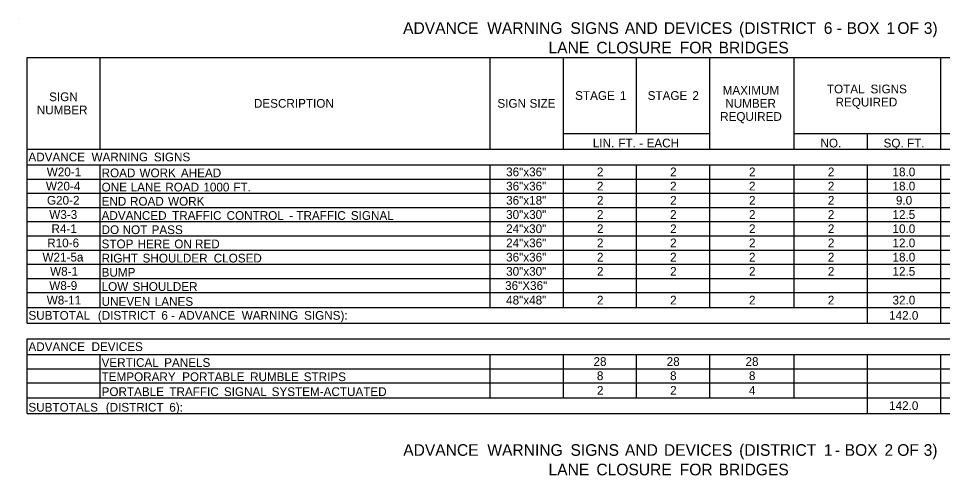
# Model space of a CAD drawing. Extents: x 542596 to 1930787, y -1948294 to 596640.
# Drawn here: x 544431 to 545065, y -1946350 to -1946037 of the extents above; entities that cross this region are included whole.
import ezdxf

# ---------------------------------------------------------------- set-up
doc = ezdxf.new("R2010")
doc.units = 0
doc.layers.add('Default', color=7, linetype='Continuous')

msp = doc.modelspace()

# ---------------------------------------------------------------- linework, layer by layer
at = {"layer": 'Default'}
for p, q in [((544430.58, -1946036.6), (544430.58, -1946036.6)), ((544436.43, -1946063.41), (545325.15, -1946063.41)), ((544436.43, -1946245.74), (544436.43, -1946063.41)), ((544436.43, -1946245.74), (544436.43, -1946063.41)), ((544486.65, -1946126.3), (544486.65, -1946063.41)), ((544754.28, -1946126.3), (544754.28, -1946063.41)), ((544804.5, -1946126.3), (544804.5, -1946063.41)), ((544854.71, -1946115.57), (544854.71, -1946063.41)), ((544904.92, -1946126.3), (544904.92, -1946063.41)), ((544962.93, -1946126.3), (544962.93, -1946063.41)), ((545063.36, -1946126.3), (545063.36, -1946063.41)), ((544804.5, -1946115.57), (544904.92, -1946115.57)), ((544904.92, -1946126.3), (544904.92, -1946115.57)), ((544962.93, -1946115.57), (545325.15, -1946115.57)), ((545013.15, -1946126.3), (545013.15, -1946115.57)), ((545063.36, -1946126.3), (545063.36, -1946115.57)), ((544436.43, -1946126.3), (545325.15, -1946126.3)), ((544904.92, -1946126.3), (545063.36, -1946126.3)), ((545063.36, -1946126.3), (545115.52, -1946126.3)), ((544436.43, -1946137.02), (545325.15, -1946137.02)), ((544486.65, -1946235.01), (544486.65, -1946137.02)), ((544486.65, -1946235.01), (544486.65, -1946137.02)), ((544754.28, -1946235.01), (544754.28, -1946137.02)), ((544754.28, -1946235.01), (544754.28, -1946137.02)), ((544804.5, -1946235.01), (544804.5, -1946137.02)), ((544804.5, -1946235.01), (544804.5, -1946137.02)), ((544854.71, -1946224.77), (544854.71, -1946137.02)), ((544854.71, -1946235.01), (544854.71, -1946137.02)), ((544904.92, -1946235.01), (544904.92, -1946137.02)), ((544904.92, -1946235.01), (544904.92, -1946137.02)), ((544962.93, -1946235.01), (544962.93, -1946137.02)), ((545013.15, -1946235.01), (545013.15, -1946137.02)), ((545013.15, -1946245.74), (545013.15, -1946137.02)), ((545063.36, -1946224.77), (545063.36, -1946137.02)), ((545063.36, -1946245.74), (545063.36, -1946137.02)), ((544436.43, -1946146.77), (545325.15, -1946146.77)), ((544436.43, -1946156.52), (545325.15, -1946156.52)), ((544436.43, -1946166.27), (545325.15, -1946166.27)), ((544436.43, -1946176.02), (545325.15, -1946176.02)), ((544436.43, -1946185.77), (545325.15, -1946185.77)), ((544436.43, -1946195.52), (545325.15, -1946195.52)), ((544436.43, -1946205.27), (545325.15, -1946205.27)), ((544436.43, -1946215.02), (545325.15, -1946215.02)), ((544436.43, -1946224.77), (545325.15, -1946224.77)), ((544436.43, -1946235.01), (545325.15, -1946235.01)), ((545013.15, -1946235.01), (545325.15, -1946235.01)), ((544436.43, -1946245.74), (545325.15, -1946245.74)), ((544436.43, -1946256.46), (545325.15, -1946256.46)), ((544436.43, -1946307.65), (544436.43, -1946256.46)), ((544436.43, -1946307.65), (544436.43, -1946256.46)), ((544486.65, -1946256.46), (545237.4, -1946256.46)), ((544436.43, -1946267.19), (545325.15, -1946267.19)), ((544486.65, -1946296.92), (544486.65, -1946267.19)), ((544486.65, -1946296.92), (544486.65, -1946267.19)), ((544754.28, -1946296.92), (544754.28, -1946267.19)), ((544754.28, -1946296.92), (544754.28, -1946267.19)), ((544804.5, -1946296.92), (544804.5, -1946267.19)), ((544804.5, -1946296.92), (544804.5, -1946267.19)), ((544854.71, -1946296.92), (544854.71, -1946267.19)), ((544854.71, -1946296.92), (544854.71, -1946267.19)), ((544904.92, -1946296.92), (544904.92, -1946267.19)), ((544904.92, -1946296.92), (544904.92, -1946267.19)), ((544962.93, -1946296.92), (544962.93, -1946267.19)), ((545013.15, -1946296.92), (545013.15, -1946267.19)), ((545013.15, -1946307.65), (545013.15, -1946267.19)), ((545063.36, -1946307.65), (545063.36, -1946267.19)), ((545063.36, -1946307.65), (545063.36, -1946267.19)), ((544436.43, -1946276.94), (545325.15, -1946276.94)), ((544436.43, -1946286.69), (545325.15, -1946286.69)), ((544436.43, -1946296.92), (545325.15, -1946296.92)), ((544436.43, -1946296.92), (545325.15, -1946296.92)), ((544436.43, -1946307.65), (545325.15, -1946307.65))]:
    msp.add_line(p, q, dxfattribs=at)

# ---------------------------------------------------------------- texts
for s, height, p in [('ADVANCE', 8, (544694.5, -1946047.18)), (' WARNING', 8, (544749.23, -1946047.18)), (' SIGNS', 8, (544806.3, -1946047.18)), (' AND', 8, (544843.64, -1946047.18)), (' DEVICES', 8, (544870.41, -1946047.18)), (' (DISTRICT', 8, (544922.04, -1946047.18)), (' 6', 8, (544980.17, -1946047.18)), (' BOX', 8, (544995.84, -1946047.18)), (' 1', 8, (545023.16, -1946047.18)), (' OF', 8, (545030.66, -1946047.18)), (' 3)', 8, (545048.77, -1946047.18)), (' -', 8, (544989.09, -1946047.18)), ('LANE', 8, (544794.26, -1946060.59)), (' CLOSURE', 8, (544824.13, -1946060.59)), (' FOR', 8, (544881.34, -1946060.59)), (' BRIDGES', 8, (544907.99, -1946060.59)), ('MAXIMUM', 6, (544913.74, -1946088.86)), ('TOTAL', 6, (544985.3, -1946087.99)), (' SIGNS', 6, (545012.99, -1946087.99)), ('SIGN', 6, (544451.63, -1946093.36)), ('STAGE', 6, (544812.55, -1946092.49)), (' 1', 6, (544841.02, -1946092.49)), ('STAGE', 6, (544862.3, -1946092.49)), (' 2', 6, (544890.77, -1946092.49)), ('DESCRIPTION', 6, (544592.15, -1946097.86)), ('SIGN', 6, (544759.2, -1946097.86)), (' SIZE', 6, (544779.03, -1946097.86)), ('NUMBER', 6, (544915.55, -1946097.86)), ('REQUIRED', 6, (544991.23, -1946096.99)), ('NUMBER', 6, (544443.16, -1946102.36)), ('REQUIRED', 6, (544912.01, -1946106.86)), ('LIN.', 6, (544824.67, -1946125.1)), (' FT.', 6, (544839.93, -1946125.1)), (' EACH', 6, (544859.31, -1946125.1)), ('NO.', 6, (544980.88, -1946125.1)), ('SQ.', 6, (545024.16, -1946125.1)), (' FT.', 6, (545038.02, -1946125.1)), (' -', 6, (544854.25, -1946125.1)), ('ADVANCE', 6, (544437.41, -1946134.66)), (' WARNING', 6, (544478.45, -1946134.66)), (' SIGNS', 6, (544521.25, -1946134.66)), ('W20-1', 6, (544449.97, -1946144.9)), ('ROAD', 6, (544487.62, -1946145.57)), (' WORK', 6, (544511.4, -1946145.57)), (' AHEAD', 6, (544539.79, -1946145.57)), ('36"x36"', 6, (544765.19, -1946144.9)), ('2', 6, (544827.49, -1946144.9)), ('2', 6, (544877.71, -1946144.9)), ('2', 6, (544931.82, -1946144.9)), ('2', 6, (544985.93, -1946144.9)), ('18.0', 6, (545030.3, -1946144.9)), ('W20-4', 6, (544449.4, -1946154.65)), ('ONE', 6, (544487.62, -1946155.32)), (' LANE', 6, (544505.34, -1946155.32)), (' ROAD', 6, (544529.12, -1946155.32)), (' 1000', 6, (544555.23, -1946155.32)), (' FT.', 6, (544575.79, -1946155.32)), ('36"x36"', 6, (544765.19, -1946154.65)), ('2', 6, (544827.49, -1946154.65)), ('2', 6, (544877.71, -1946154.65)), ('2', 6, (544931.82, -1946154.65)), ('2', 6, (544985.93, -1946154.65)), ('18.0', 6, (545030.3, -1946154.65)), ('G20-2', 6, (544450.12, -1946164.4)), ('END', 6, (544487.62, -1946165.07)), (' ROAD', 6, (544504.88, -1946165.07)), (' WORK', 6, (544530.98, -1946165.07)), ('36"x18"', 6, (544765.19, -1946164.4)), ('2', 6, (544827.49, -1946164.4)), ('2', 6, (544877.71, -1946164.4)), ('2', 6, (544931.82, -1946164.4)), ('2', 6, (544985.93, -1946164.4)), ('9.0', 6, (545032.63, -1946164.4)), ('W3-3', 6, (544451.72, -1946174.15)), ('ADVANCED', 6, (544487.62, -1946174.82)), (' TRAFFIC', 6, (544533.77, -1946174.82)), (' CONTROL', 6, (544571.16, -1946174.82)), (' -', 6, (544614.18, -1946174.82)), (' TRAFFIC', 6, (544619.03, -1946174.82)), (' SIGNAL', 6, (544656.42, -1946174.82)), ('30"x30"', 6, (544765.19, -1946174.15)), ('2', 6, (544827.49, -1946174.15)), ('2', 6, (544877.71, -1946174.15)), ('2', 6, (544931.82, -1946174.15)), ('2', 6, (544985.93, -1946174.15)), ('12.5', 6, (545030.27, -1946174.15)), ('R4-1', 6, (544453.23, -1946183.9)), ('DO', 6, (544487.62, -1946184.57)), (' NOT', 6, (544499.82, -1946184.57)), (' PASS', 6, (544519.68, -1946184.57)), ('24"x30"', 6, (544765.19, -1946183.9)), ('2', 6, (544827.49, -1946183.9)), ('2', 6, (544877.71, -1946183.9)), ('2', 6, (544931.82, -1946183.9)), ('2', 6, (544985.93, -1946183.9)), ('10.0', 6, (545030.3, -1946183.9)), ('R10-6', 6, (544450.32, -1946193.65)), ('STOP', 6, (544487.62, -1946194.32)), (' HERE', 6, (544510.09, -1946194.32)), (' ON', 6, (544535.26, -1946194.32)), (' RED', 6, (544549.48, -1946194.32)), ('24"x36"', 6, (544765.19, -1946193.65)), ('2', 6, (544827.49, -1946193.65)), ('2', 6, (544877.71, -1946193.65)), ('2', 6, (544931.82, -1946193.65)), ('2', 6, (544985.93, -1946193.65)), ('12.0', 6, (545030.3, -1946193.65)), ('W21-5a', 6, (544447.05, -1946203.4)), ('36"x36"', 6, (544765.19, -1946203.4)), ('2', 6, (544827.49, -1946203.4)), ('2', 6, (544877.71, -1946203.4)), ('2', 6, (544931.82, -1946203.4)), ('2', 6, (544985.93, -1946203.4)), ('18.0', 6, (545030.3, -1946203.4)), ('RIGHT', 6, (544487.62, -1946204.07)), (' SHOULDER', 6, (544513.53, -1946204.07)), (' CLOSED', 6, (544562.33, -1946204.07)), ('W8-1', 6, (544452.3, -1946213.15)), ('BUMP', 6, (544487.62, -1946213.82)), ('30"x30"', 6, (544765.19, -1946213.15)), ('2', 6, (544827.49, -1946213.15)), ('2', 6, (544877.71, -1946213.15)), ('2', 6, (544931.82, -1946213.15)), ('2', 6, (544985.93, -1946213.15)), ('12.5', 6, (545030.27, -1946213.15)), ('W8-9', 6, (544451.72, -1946222.9)), ('LOW', 6, (544487.62, -1946223.57)), (' SHOULDER', 6, (544506.62, -1946223.57)), ('36"X36"', 6, (544764.49, -1946222.9)), ('W8-11', 6, (544449.97, -1946232.89)), ('UNEVEN', 6, (544487.62, -1946233.81)), (' LANES', 6, (544521.88, -1946233.81)), ('48"x48"', 6, (544765.19, -1946232.89)), ('2', 6, (544827.49, -1946232.89)), ('2', 6, (544877.71, -1946232.89)), ('2', 6, (544931.82, -1946232.89)), ('2', 6, (544985.93, -1946232.89)), ('32.0', 6, (545030.3, -1946232.89)), ('SUBTOTAL', 6, (544437.41, -1946243.37)), (' (DISTRICT', 6, (544482.8, -1946243.37)), (' 6', 6, (544526.4, -1946243.37)), (' -', 6, (544533.09, -1946243.37)), (' ADVANCE', 6, (544538.15, -1946243.37)), (' WARNING', 6, (544581.52, -1946243.37)), (' SIGNS):', 6, (544624.32, -1946243.37)), ('142.0', 6, (545027.97, -1946243.37)), ('ADVANCE', 6, (544437.41, -1946264.82)), (' DEVICES', 6, (544478.45, -1946264.82)), ('VERTICAL', 6, (544487.62, -1946275.74)), (' PANELS', 6, (544528.32, -1946275.74)), ('28', 6, (544825.13, -1946275.06)), ('28', 6, (544875.34, -1946275.06)), ('28', 6, (544929.45, -1946275.06)), ('TEMPORARY', 6, (544487.62, -1946285.49)), (' PORTABLE', 6, (544540.67, -1946285.49)), (' RUMBLE', 6, (544587.28, -1946285.49)), (' STRIPS', 6, (544624.09, -1946285.49)), ('8', 6, (544827.46, -1946284.81)), ('8', 6, (544877.67, -1946284.81)), ('8', 6, (544931.78, -1946284.81)), ('PORTABLE', 6, (544487.62, -1946295.72)), (' TRAFFIC', 6, (544531.9, -1946295.72)), (' SIGNAL', 6, (544569.29, -1946295.72)), (' SYSTEM-ACTUATED', 6, (544602.07, -1946295.72)), ('2', 6, (544827.49, -1946294.81)), ('2', 6, (544877.71, -1946294.81)), ('4', 6, (544931.8, -1946294.81)), ('142.0', 6, (545027.97, -1946305.29)), ('SUBTOTALS', 6, (544437.41, -1946306.45)), (' (DISTRICT', 6, (544488.24, -1946306.45)), (' 6):', 6, (544531.84, -1946306.45)), ('ADVANCE', 8, (544694.59, -1946336.76)), (' WARNING', 8, (544749.31, -1946336.76)), (' SIGNS', 8, (544806.38, -1946336.76)), (' AND', 8, (544843.72, -1946336.76)), (' DEVICES', 8, (544870.49, -1946336.76)), (' (DISTRICT', 8, (544922.12, -1946336.76)), (' 1', 8, (544980.26, -1946336.76)), (' BOX', 8, (544994.51, -1946336.76)), (' 2', 8, (545021.82, -1946336.76)), (' OF', 8, (545030.58, -1946336.76)), (' 3)', 8, (545048.69, -1946336.76)), (' -', 8, (544987.76, -1946336.76)), ('LANE', 8, (544794.26, -1946350.16)), (' CLOSURE', 8, (544824.13, -1946350.16)), (' FOR', 8, (544881.34, -1946350.16)), (' BRIDGES', 8, (544907.99, -1946350.16))]:
    msp.add_text(s, height=height, dxfattribs=at).set_placement(p)

doc.saveas('drawing.dxf')
